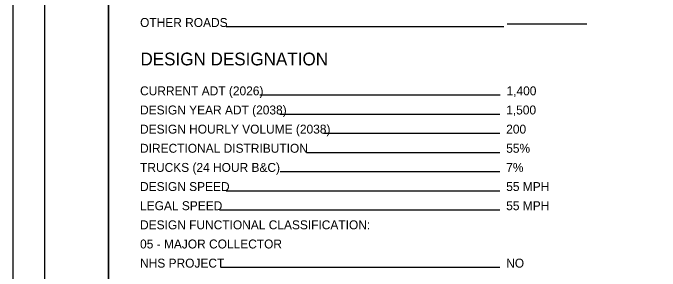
# Model space of a CAD drawing. Extents: x 0 to 34, y 0 to 22.
# Drawn here: x 0 to 10.15, y 7.05 to 11.1 of the extents above; entities that cross this region are included whole.
import ezdxf

# ---------------------------------------------------------------- set-up
doc = ezdxf.new("R2010")
doc.units = 0
for name, color, linetype in [('SH_Border', 7, 'Continuous'), ('SH_Cut_Line', 7, 'Continuous'), ('SH_Data', 7, 'Continuous'), ('SH_Text', 7, 'Continuous')]:
    doc.layers.add(name, color=color, linetype=linetype)

msp = doc.modelspace()

# ---------------------------------------------------------------- linework, layer by layer
at = {"layer": 'SH_Border'}
for points in [[(0.5, 21.5), (1.5, 21.5), (1.5, 0.5), (0.5, 0.5)], [(1.5, 21.5), (33.5, 21.5), (33.5, 0.5), (1.5, 0.5)]]:
    msp.add_lwpolyline(points, close=True, dxfattribs=at)
at = {"layer": 'SH_Cut_Line'}
msp.add_lwpolyline([(0, 0), (34, 0), (34, 22), (0, 22)], close=True, dxfattribs=at)
at = {"layer": 'SH_Data'}
for p, q in [((7.7, 10.877), (3.347, 10.877)), ((9, 10.922), (7.75, 10.922)), ((7.642, 9.806), (3.871, 9.806)), ((7.637, 9.506), (4.189, 9.506)), ((7.637, 9.206), (4.872, 9.206)), ((7.637, 8.906), (4.604, 8.906)), ((7.637, 8.606), (4.189, 8.606)), ((7.637, 8.306), (3.346, 8.306)), ((7.637, 8.006), (3.242, 8.006)), ((7.637, 7.106), (3.267, 7.106))]:
    msp.add_line(p, q, dxfattribs=at)

# ---------------------------------------------------------------- texts
msp.add_text('DESIGN DESIGNATION', height=0.2, dxfattribs=at).set_placement((2, 10.275))
at = {"layer": 'SH_Text'}
for s, p in [('OTHER ROADS', (1.994, 10.877)), ('CURRENT ADT (2026)', (1.994, 9.806)), ('1,400', (7.742, 9.806)), ('DESIGN YEAR ADT (2038)', (1.994, 9.506)), ('1,500', (7.737, 9.506)), ('DESIGN HOURLY VOLUME (2038)', (1.994, 9.206)), ('200', (7.737, 9.206)), ('DIRECTIONAL DISTRIBUTION', (1.994, 8.906)), ('55%', (7.737, 8.906)), ('TRUCKS (24 HOUR B&C)', (1.994, 8.606)), ('7%', (7.737, 8.606)), ('DESIGN SPEED', (1.994, 8.306)), ('55 MPH', (7.737, 8.306)), ('LEGAL SPEED', (1.994, 8.006)), ('55 MPH', (7.737, 8.006)), ('DESIGN FUNCTIONAL CLASSIFICATION:', (1.994, 7.706)), ('05 - MAJOR COLLECTOR', (1.994, 7.406)), ('NHS PROJECT', (1.994, 7.106)), ('NO', (7.737, 7.106))]:
    msp.add_text(s, height=0.14, dxfattribs=at).set_placement(p)

doc.saveas('drawing.dxf')
